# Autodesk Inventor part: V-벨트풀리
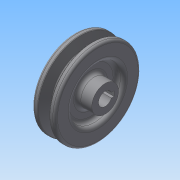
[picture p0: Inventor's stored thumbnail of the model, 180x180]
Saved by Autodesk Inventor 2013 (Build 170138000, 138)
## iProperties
Created: 2015-02
Part Number: V-벨트풀리
Material: 일반
Document SubType Name: Modeling
Designer: Administrator
Density: 1 g/cm^3
Author: Administrator
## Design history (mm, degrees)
sketch "스케치1"
  geometry: L1 (0, 0)-(25, 0); L2 (0, 5.5)-(25, 5.5); L3 (25, 5.5)-(25, 11); L4 (25, 11)-(13, 11); L5 (13, 11)-(13, 21.5); L6 (13, 21.5)-(19, 21.5); L7 (19, 21.5)-(19, 35.2); L8 (19, 35.2)-(14.325, 35.2); L9 (14.325, 35.2)-(11.574, 26.2); L10 (11.574, 26.2)-(7.426, 26.2); L11 (7.426, 26.2)-(4.675, 35.2); L12 (4.675, 35.2)-(0, 35.2); L13 (0, 35.2)-(0, 21.5); L14 (0, 21.5)-(6, 21.5); L15 (6, 21.5)-(6, 11); L16 (6, 11)-(0, 11); L17 (0, 11)-(0, 5.5); 2 further points
  constraints: 34 end point, 5 parallel, 4 horizontal alignment, 3 equal length, 3 horizontal, 3 perpendicular, 3 vertical, 3 vertical alignment, 2 point on line
  dimensions: "d0" = 25 distance of L1.start L1.end; "d1" = 8 distance of point (13.5, 32.5) point (5.5, 32.5); "d2" = 34 deg angle of L9 L11; "d3" = 6.3 distance from line of L10 point (13.5, 32.5); "d4" = 2.7 vertical distance of L8.end point (13.5, 32.5); "d5" = 19 distance between parallel lines of L7 L13; "d6" = 6 distance of L13.end L14.end; "d7" = 43 diameter of L14 L1; "d8" = 11 diameter of L2 L1; "d9" = 22 diameter of L4 L1; "d10" = 65 diameter of point (5.5, 32.5) L1
revolve "회전1" sketch "스케치1" stored, may be unused: angle "d11" = 90 deg
sketch "스케치2"
  geometry: L1 (-2, 5.123)-(-2, 7.3); L2 (-2, 7.3)-(2, 7.3); L3 (2, 7.3)-(2, 5.123); A1 r 5.5 centre (0, 0) between (-2, 5.123) and (2, 5.123) reference; 1 further point
  constraints: 6 end point, 2 parallel, 2 point on circle, 1 midpoint, 1 perpendicular, 1 vertical alignment
  dimensions: "d12" = 4 distance of L1.end L2.end; "d14" = 12.8 dimension on A1 L2
extrude "돌출1" cut sketch "스케치2" stored distance "d15" = 10; taper "d16" = 0 deg
fillet "모깎기1" dims "d17" = 2, "d18" = 0.5, "d19" = 1, "d20" = 3
node "솔리드1"
